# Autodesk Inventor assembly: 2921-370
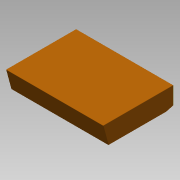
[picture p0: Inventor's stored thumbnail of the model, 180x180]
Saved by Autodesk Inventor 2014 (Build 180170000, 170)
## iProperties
Company: NHTSA/VRTC
Created: 2012-02
Part Number: 2921-370
Document SubType Name: Assembly
Designer: Mike Vanvoorhis
Project: CHILD SIDE IMPACT SLED
Description: BOTTOM SEAT CUSHION ASS'Y.
Mass: 29439.3 g
Surface Area: 36585.5 cm^2
Volume: 44147.3 cm^3
Density: 0.666841 g/cm^3
Title: Seat Bottom Cushion Assembly
Subject: Child Side Impact Sled
Author: Dave Walker
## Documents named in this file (4)
- B:\VRTC_DWG\BIO\Non-P572\Child Side-Frontal Impact Sled\Side Impact Sled\Bottom_Seat_Cushion_Assembly.iam
- B:\VRTC_DWG\BIO\Non-P572\Child Side-Frontal Impact Sled\Side Impact Sled\Seat_Bottom_Cushion_Mounting_Plate_Assembly.iam
- B:\VRTC_DWG\BIO\Non-P572\Child Side-Frontal Impact Sled\Side Impact Sled\Bottom_Seat_Cushion_Cover.ipt
- B:\VRTC_DWG\BIO\Non-P572\Child Side-Frontal Impact Sled\Side Impact Sled\Seat_Bottom_Cushion.ipt
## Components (3 placed, 3 different names)
1. Seat_Bottom_Cushion_Mounting_Plate_Assembly:1 [sub-assembly] — Mate:1, Mate:9, Mate:10
2. Seat_Bottom_Cushion:1 — Mate:1, Flush:5, Mate:8, Mate:9
3. Bottom_Seat_Cushion_Cover:1 — Mate:8, Mate:10, Flush:6
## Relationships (6: Mate 4, Flush 2)
- Mate:1: Seat_Bottom_Cushion_Mounting_Plate_Assembly:1 ↔ Seat_Bottom_Cushion:1
- Flush:5: Seat_Bottom_Cushion:1
- Mate:8: Seat_Bottom_Cushion:1 ↔ Bottom_Seat_Cushion_Cover:1
- Mate:9: Seat_Bottom_Cushion_Mounting_Plate_Assembly:1 ↔ Seat_Bottom_Cushion:1
- Mate:10: Seat_Bottom_Cushion_Mounting_Plate_Assembly:1 ↔ Bottom_Seat_Cushion_Cover:1
- Flush:6: Bottom_Seat_Cushion_Cover:1
